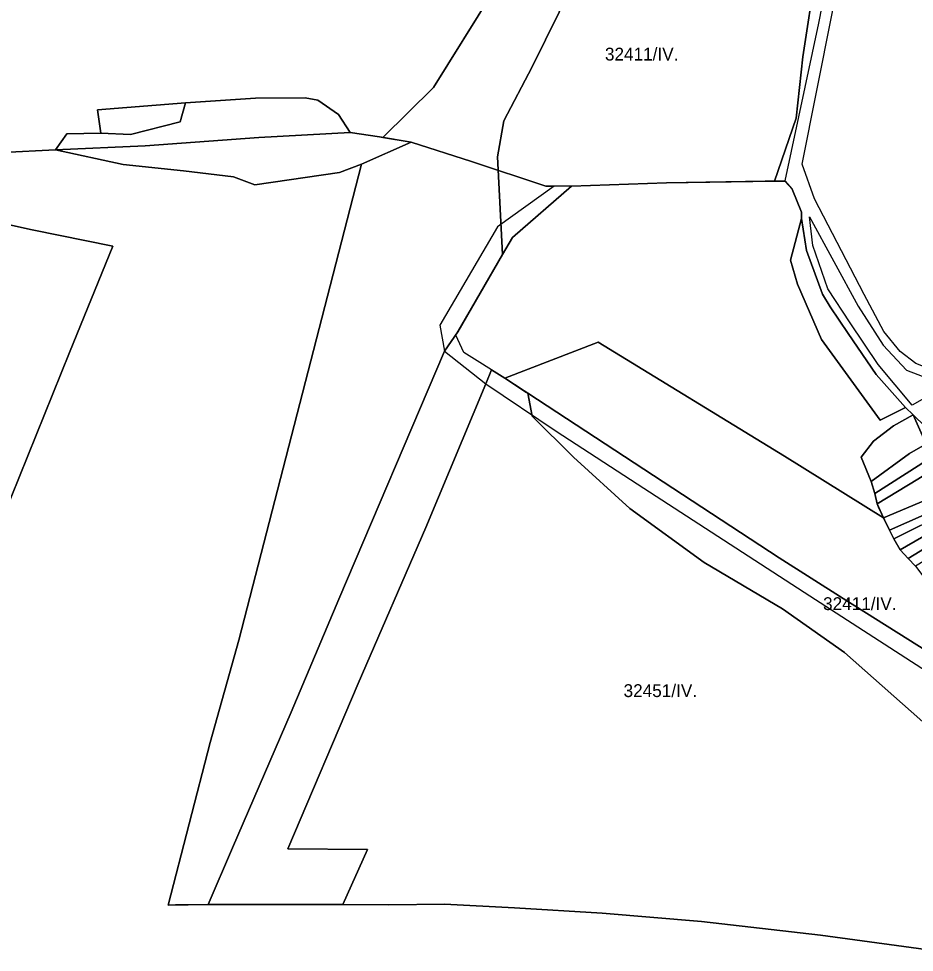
# Model space of a CAD drawing. Extents: x -532083 to -529270, y -1180561 to -1176456.
# Drawn here: x -530643.9 to -530295.1, y -1179343.8 to -1178980.2 of the extents above; entities that cross this region are included whole.
import ezdxf

# ---------------------------------------------------------------- set-up
doc = ezdxf.new("R2010")
doc.units = 0
for name, color, linetype in [('95560013', 7, 'Continuous'), ('95590013', 7, 'Continuous'), ('95610013', 7, 'Continuous'), ('95620013', 7, 'Continuous'), ('95660013', 7, 'Continuous')]:
    doc.layers.add(name, color=color, linetype=linetype)

msp = doc.modelspace()

# ---------------------------------------------------------------- linework, layer by layer
at = {"layer": '95560013'}
for points in [[(-530321.3073, -1178925.52945), (-530332.4003, -1178981.99545), (-530345.5483, -1179043.40645), (-530391.6263, -1179044.11145), (-530428.5473, -1179045.37145), (-530438.5943, -1179045.37145), (-530467.4773, -1179035.79645), (-530491.0873, -1179028.23845), (-530503.3233, -1179026.20245), (-530514.7293, -1179024.56745), (-530519.2893, -1179017.55745), (-530527.3723, -1179011.89745), (-530532.2523, -1179010.97945), (-530551.6213, -1179011.13245), (-530578.9203, -1179012.96845), (-530613.2353, -1179015.72145), (-530611.8623, -1179024.74845), (-530625.1313, -1179025.05445), (-530629.4813, -1179031.33945), (-530650.1973, -1179032.27345), (-530668.8183, -1179034.60845), (-530710.4553, -1179041.28045), (-530690.5463, -1179014.35945), (-530643.5763, -1178951.29245)], [(-530239.7833, -1178962.37045), (-530242.1383, -1179023.22645), (-530239.1813, -1179047.63845), (-530228.8463, -1179092.36745), (-530242.4243, -1179095.93945), (-530255.5573, -1179104.87145), (-530273.5863, -1179114.69645), (-530286.4973, -1179117.59945), (-530294.5103, -1179114.47345), (-530300.5203, -1179109.78445), (-530306.9753, -1179101.96845), (-530314.5433, -1179087.67845), (-530333.9393, -1179050.34045), (-530338.6833, -1179036.85645), (-530321.3203, -1178949.31245)], [(-530713.8673, -1179045.84445), (-530638.6183, -1179062.40745), (-530607.2773, -1179068.78745), (-530624.0833, -1179110.25145), (-530692.4043, -1179279.29745)]]:
    msp.add_lwpolyline(points, dxfattribs=at)
at = {"layer": '95590013'}
for points in [[(-530293.6203, -1179154.37445), (-530310.4393, -1179165.17445), (-530311.8943, -1179160.43045), (-530296.9343, -1179149.54845), (-530286.2723, -1179143.47045), (-530282.6063, -1179147.29045)], [(-530293.7273, -1179159.52245), (-530309.5303, -1179169.18845), (-530310.4393, -1179165.17445), (-530293.6203, -1179154.37445), (-530282.6063, -1179147.29045), (-530279.3623, -1179150.54345)], [(-530288.2353, -1179166.62945), (-530307.1133, -1179174.58145), (-530309.5303, -1179169.18845), (-530293.7273, -1179159.52245), (-530279.3623, -1179150.54345), (-530272.4533, -1179157.33345)], [(-530283.2513, -1179169.96245), (-530304.7083, -1179179.40645), (-530307.1133, -1179174.58145), (-530288.2353, -1179166.62945), (-530272.4533, -1179157.33345), (-530267.9413, -1179161.01145)], [(-530281.5903, -1179172.18445), (-530303.0243, -1179182.78445), (-530304.7083, -1179179.40645), (-530283.2513, -1179169.96245), (-530267.9413, -1179161.01145), (-530266.1073, -1179162.42545)], [(-530281.4793, -1179176.07345), (-530300.6193, -1179187.12745), (-530303.0243, -1179182.78445), (-530281.5903, -1179172.18445), (-530266.1073, -1179162.42545), (-530263.1463, -1179164.54745)], [(-530277.7133, -1179178.40645), (-530297.4933, -1179190.50445), (-530300.6193, -1179187.12745), (-530281.4793, -1179176.07345), (-530263.1463, -1179164.54745), (-530260.0443, -1179167.09345)], [(-530274.7233, -1179181.29545), (-530294.6073, -1179193.40045), (-530297.4933, -1179190.50445), (-530277.7133, -1179178.40645), (-530260.0443, -1179167.09345), (-530255.6733, -1179170.91345)]]:
    msp.add_lwpolyline(points, close=True, dxfattribs=at)
at = {"layer": '95610013'}
for points in [[(-530569.3263, -1179262.08445), (-530558.1493, -1179222.29945), (-530520.3563, -1179075.69445), (-530510.4263, -1179036.80445), (-530491.0873, -1179028.23845), (-530467.4773, -1179035.79645), (-530438.5943, -1179045.37145), (-530435.3293, -1179045.37145), (-530457.3843, -1179061.31545), (-530479.8873, -1179099.61445), (-530478.0863, -1179109.65945), (-530519.1543, -1179206.25045), (-530537.7453, -1179250.23245), (-530560.6433, -1179303.16745), (-530570.0483, -1179325.25645), (-530585.6813, -1179325.42545)], [(-530454.6033, -1179120.15945), (-530470.5323, -1179110.26745), (-530473.5663, -1179103.41945), (-530451.5693, -1179065.37345), (-530428.5473, -1179045.37145), (-530391.6263, -1179044.11145), (-530345.5483, -1179043.40645), (-530342.5903, -1179046.59145), (-530339.0283, -1179055.52345), (-530339.0283, -1179057.97945), (-530343.2583, -1179074.28045), (-530340.5863, -1179083.65845), (-530331.2383, -1179105.09445), (-530308.3113, -1179136.57945), (-530298.5173, -1179131.66645), (-530295.5263, -1179134.52345), (-530303.1643, -1179138.72045), (-530310.9853, -1179144.74045), (-530315.7133, -1179150.94345), (-530311.8943, -1179160.43045), (-530310.4393, -1179165.17445), (-530309.5303, -1179169.18845), (-530307.1133, -1179174.58145), (-530345.6303, -1179150.59545), (-530418.1953, -1179106.20945)], [(-530308.3113, -1179136.57945), (-530331.2383, -1179105.09445), (-530340.5863, -1179083.65845), (-530343.2583, -1179074.28045), (-530339.0283, -1179057.97945), (-530337.0253, -1179070.48445), (-530330.7923, -1179087.45445), (-530327.8993, -1179092.36745), (-530320.7763, -1179102.86145), (-530309.8693, -1179118.71545), (-530298.5173, -1179131.66645)], [(-530295.8463, -1179130.77345), (-530309.2013, -1179114.91945), (-530320.1083, -1179098.61945), (-530328.7893, -1179085.44545), (-530334.5763, -1179068.47445), (-530335.9123, -1179057.31045), (-530316.9923, -1179092.14345), (-530307.1983, -1179107.32745), (-530298.0713, -1179117.15245), (-530287.6103, -1179121.17245), (-530276.7033, -1179119.83245)], [(-530347.6493, -1179190.15545), (-530454.6033, -1179120.15945), (-530418.1953, -1179106.20945), (-530345.6303, -1179150.59545), (-530307.1133, -1179174.58145), (-530304.7083, -1179179.40645), (-530303.0243, -1179182.78445), (-530300.6193, -1179187.12745), (-530297.4933, -1179190.50445), (-530294.6073, -1179193.40045), (-530289.0753, -1179200.87945), (-530286.1893, -1179205.22245), (-530283.5433, -1179209.56445), (-530281.1383, -1179213.90745), (-530278.0123, -1179218.97445), (-530270.7973, -1179225.48845), (-530263.8223, -1179231.27845), (-530270.3163, -1179240.44645), (-530284.9993, -1179229.75745), (-530322.8373, -1179205.97545)], [(-530311.8943, -1179160.43045), (-530315.7133, -1179150.94345), (-530310.9853, -1179144.74045), (-530303.1643, -1179138.72045), (-530295.5263, -1179134.52345), (-530286.2723, -1179143.47045), (-530296.9343, -1179149.54845)]]:
    msp.add_lwpolyline(points, close=True, dxfattribs=at)
msp.add_lwpolyline([(-530282.9893, -1179343.83245), (-530331.5983, -1179337.14345), (-530377.9583, -1179331.84545), (-530416.6893, -1179328.60745), (-530450.7263, -1179326.54745), (-530478.0133, -1179325.07545), (-530499.7263, -1179325.37045), (-530517.5983, -1179325.25645), (-530508.0163, -1179303.83945), (-530539.1163, -1179303.50245), (-530511.7153, -1179239.08245), (-530485.3013, -1179178.41445), (-530461.9923, -1179122.46445), (-530434.4913, -1179140.79645), (-530400.4293, -1179163.00045), (-530335.7333, -1179204.98045), (-530273.4423, -1179245.27145)], dxfattribs=at)
at = {"layer": '95620013'}
for points in [[(-530550.3423, -1179026.43545), (-530594.5673, -1179029.70445), (-530629.4813, -1179031.33945), (-530625.1313, -1179025.05445), (-530611.8623, -1179024.74845), (-530600.2723, -1179025.36045), (-530581.0553, -1179020.31145), (-530578.9203, -1179012.96845), (-530551.6213, -1179011.13245), (-530532.2523, -1179010.97945), (-530527.3723, -1179011.89745), (-530519.2893, -1179017.55745), (-530514.7293, -1179024.56745)], [(-530581.0553, -1179020.31145), (-530600.2723, -1179025.36045), (-530611.8623, -1179024.74845), (-530613.2353, -1179015.72145), (-530578.9203, -1179012.96845)], [(-530551.8683, -1179044.86745), (-530560.1563, -1179041.84345), (-530579.6703, -1179039.51145), (-530603.1793, -1179036.94345), (-530629.4813, -1179031.33945), (-530594.5673, -1179029.70445), (-530550.3423, -1179026.43545), (-530514.7293, -1179024.56745), (-530503.3233, -1179026.20245), (-530491.0873, -1179028.23845), (-530510.4263, -1179036.80445), (-530518.9663, -1179040.07945)], [(-530537.7453, -1179250.23245), (-530519.1543, -1179206.25045), (-530478.0863, -1179109.65945), (-530461.9923, -1179122.46445), (-530485.3013, -1179178.41445), (-530511.7153, -1179239.08245), (-530539.1163, -1179303.50245), (-530508.0163, -1179303.83945), (-530517.5983, -1179325.25645), (-530570.0483, -1179325.25645), (-530560.6433, -1179303.16745)]]:
    msp.add_lwpolyline(points, close=True, dxfattribs=at)
for points in [[(-530650.1973, -1179032.27345), (-530629.4813, -1179031.33945), (-530603.1793, -1179036.94345), (-530579.6703, -1179039.51145), (-530560.1563, -1179041.84345), (-530551.8683, -1179044.86745), (-530518.9663, -1179040.07945), (-530510.4263, -1179036.80445), (-530520.3563, -1179075.69445), (-530558.1493, -1179222.29945), (-530569.3263, -1179262.08445), (-530585.6813, -1179325.42545), (-530570.0483, -1179325.25645), (-530517.5983, -1179325.25645), (-530499.7263, -1179325.37045), (-530478.0133, -1179325.07545), (-530450.7263, -1179326.54745), (-530416.6893, -1179328.60745), (-530377.9583, -1179331.84545), (-530331.5983, -1179337.14345), (-530282.9893, -1179343.83245)], [(-530692.4043, -1179279.29745), (-530624.0833, -1179110.25145), (-530607.2773, -1179068.78745), (-530638.6183, -1179062.40745), (-530713.8673, -1179045.84445)]]:
    msp.add_lwpolyline(points, dxfattribs=at)
at = {"layer": '95660013'}
for points in [[(-530333.3753, -1178962.00045), (-530338.5003, -1178995.00045), (-530341.1253, -1179019.00045), (-530349.5233, -1179043.46745), (-530391.6263, -1179044.11145), (-530428.5473, -1179045.37145), (-530451.5693, -1179065.37345), (-530455.4543, -1179072.09245), (-530457.3753, -1179034.00045), (-530454.8753, -1179020.00045), (-530443.8753, -1178999.00045), (-530428.1873, -1178967.00045)], [(-530290.8753, -1179145.00045), (-530295.5263, -1179134.52345), (-530298.5173, -1179131.66645), (-530309.8693, -1179118.71545), (-530320.7763, -1179102.86145), (-530327.8993, -1179092.36745), (-530330.7923, -1179087.45445), (-530337.0253, -1179070.48445), (-530339.0283, -1179057.97945), (-530339.0283, -1179055.52345), (-530342.5903, -1179046.59145), (-530345.5203, -1179043.43745), (-530349.5233, -1179043.46745), (-530341.1253, -1179019.00045), (-530338.5003, -1178995.00045), (-530333.3753, -1178962.00045)], [(-530428.1873, -1178967.00045), (-530443.8753, -1178999.00045), (-530454.8753, -1179020.00045), (-530457.3753, -1179034.00045), (-530455.4543, -1179072.09245), (-530472.8493, -1179102.17845), (-530478.0863, -1179109.65945), (-530519.1543, -1179206.25045), (-530537.7453, -1179250.23245), (-530560.6433, -1179303.16745), (-530570.0483, -1179325.25645), (-530579.6963, -1179325.36045), (-530582.8543, -1179325.39445), (-530585.6813, -1179325.42545), (-530569.3263, -1179262.08445), (-530558.1493, -1179222.29945), (-530520.3563, -1179075.69445), (-530510.4263, -1179036.80445), (-530491.0873, -1179028.23845), (-530502.0713, -1179026.41045), (-530482.3753, -1179007.00045), (-530459.3753, -1178970.00045)], [(-530459.3753, -1178970.00045), (-530482.3753, -1179007.00045), (-530502.0713, -1179026.41045), (-530503.3233, -1179026.20245), (-530514.7293, -1179024.56745), (-530519.2893, -1179017.55745), (-530527.3723, -1179011.89745), (-530532.2523, -1179010.97945), (-530551.6213, -1179011.13245), (-530578.9203, -1179012.96845), (-530581.0553, -1179020.31145), (-530600.2723, -1179025.36045), (-530611.8623, -1179024.74845), (-530625.1313, -1179025.05445), (-530629.4813, -1179031.33945), (-530650.1973, -1179032.27345)], [(-530650.1973, -1179032.27345), (-530629.4813, -1179031.33945), (-530625.1313, -1179025.05445), (-530611.8623, -1179024.74845), (-530600.2723, -1179025.36045), (-530581.0553, -1179020.31145), (-530578.9203, -1179012.96845), (-530551.6213, -1179011.13245), (-530532.2523, -1179010.97945), (-530527.3723, -1179011.89745), (-530519.2893, -1179017.55745), (-530514.7293, -1179024.56745), (-530503.3233, -1179026.20245), (-530502.0713, -1179026.41045), (-530491.0873, -1179028.23845), (-530510.4263, -1179036.80445), (-530520.3563, -1179075.69445), (-530558.1493, -1179222.29945), (-530569.3263, -1179262.08445), (-530585.6813, -1179325.42545), (-530582.8543, -1179325.39445), (-530579.6963, -1179325.36045), (-530570.0483, -1179325.25645), (-530560.6433, -1179303.16745), (-530537.7453, -1179250.23245), (-530519.1543, -1179206.25045), (-530478.0863, -1179109.65945), (-530472.8493, -1179102.17845), (-530455.4543, -1179072.09245), (-530451.5693, -1179065.37345), (-530428.5473, -1179045.37145), (-530391.6263, -1179044.11145), (-530349.5233, -1179043.46745), (-530345.5203, -1179043.43745), (-530342.5903, -1179046.59145), (-530339.0283, -1179055.52345), (-530339.0283, -1179057.97945), (-530337.0253, -1179070.48445), (-530330.7923, -1179087.45445), (-530327.8993, -1179092.36745), (-530320.7763, -1179102.86145), (-530309.8693, -1179118.71545), (-530298.5173, -1179131.66645), (-530295.5263, -1179134.52345), (-530303.1643, -1179138.72045), (-530310.9853, -1179144.74045), (-530315.7133, -1179150.94345), (-530311.8943, -1179160.43045), (-530310.4393, -1179165.17445), (-530309.5303, -1179169.18845), (-530308.9903, -1179170.39245), (-530305.4793, -1179177.85945), (-530304.7083, -1179179.40645), (-530303.0243, -1179182.78445), (-530300.6193, -1179187.12745), (-530297.4933, -1179190.50445), (-530294.6073, -1179193.40045)], [(-530692.4043, -1179279.29745), (-530624.0833, -1179110.25145), (-530607.2773, -1179068.78745), (-530638.6183, -1179062.40745), (-530713.8673, -1179045.84445)], [(-530713.8673, -1179045.84445), (-530638.6183, -1179062.40745), (-530607.2773, -1179068.78745), (-530624.0833, -1179110.25145), (-530692.4043, -1179279.29745)], [(-530284.9993, -1179229.75745), (-530322.8373, -1179205.97545), (-530347.6493, -1179190.15545), (-530445.5953, -1179126.05445), (-530446.0883, -1179125.73245), (-530454.6033, -1179120.15945), (-530459.7103, -1179116.98745), (-530461.9923, -1179122.46445), (-530485.3013, -1179178.41445), (-530511.7153, -1179239.08245), (-530539.1163, -1179303.50245), (-530508.0163, -1179303.83945), (-530517.5983, -1179325.25645), (-530499.7263, -1179325.37045), (-530478.0133, -1179325.07545), (-530450.7263, -1179326.54745), (-530416.6893, -1179328.60745), (-530377.9583, -1179331.84545), (-530331.5983, -1179337.14345), (-530282.9893, -1179343.83245)], [(-530282.9893, -1179343.83245), (-530331.5983, -1179337.14345), (-530377.9583, -1179331.84545), (-530416.6893, -1179328.60745), (-530450.7263, -1179326.54745), (-530478.0133, -1179325.07545), (-530499.7263, -1179325.37045), (-530517.5983, -1179325.25645), (-530508.0163, -1179303.83945), (-530539.1163, -1179303.50245), (-530511.7153, -1179239.08245), (-530485.3013, -1179178.41445), (-530461.9923, -1179122.46445), (-530459.7103, -1179116.98745), (-530454.6033, -1179120.15945), (-530446.0883, -1179125.73245), (-530445.5953, -1179126.05445), (-530443.8753, -1179135.00045), (-530427.8123, -1179151.00045), (-530405.8123, -1179171.00045), (-530376.8753, -1179192.00045), (-530346.3753, -1179210.00045), (-530322.3123, -1179227.00045), (-530288.3753, -1179257.00045)], [(-530288.3753, -1179257.00045), (-530322.3123, -1179227.00045), (-530346.3753, -1179210.00045), (-530376.8753, -1179192.00045), (-530405.8123, -1179171.00045), (-530427.8123, -1179151.00045), (-530443.8753, -1179135.00045), (-530445.5953, -1179126.05445), (-530347.6493, -1179190.15545), (-530322.8373, -1179205.97545), (-530284.9993, -1179229.75745)], [(-530294.6073, -1179193.40045), (-530297.4933, -1179190.50445), (-530300.6193, -1179187.12745), (-530303.0243, -1179182.78445), (-530304.7083, -1179179.40645), (-530305.4793, -1179177.85945), (-530308.9903, -1179170.39245), (-530309.5303, -1179169.18845), (-530310.4393, -1179165.17445), (-530311.8943, -1179160.43045), (-530315.7133, -1179150.94345), (-530310.9853, -1179144.74045), (-530303.1643, -1179138.72045), (-530295.5263, -1179134.52345), (-530290.8753, -1179145.00045)]]:
    msp.add_lwpolyline(points, dxfattribs=at)

# ---------------------------------------------------------------- texts
for s, rotation, p in [('32411/IV.', 0, (-530415.5628, -1178996.48282)), ('32411/IV.', 0, (-530330.61213, -1179210.52745)), ('32451/IV.', 360, (-530408.30025, -1179244.40845))]:
    msp.add_text(s, height=5, rotation=rotation, dxfattribs=at).set_placement(p)

doc.saveas('drawing.dxf')
